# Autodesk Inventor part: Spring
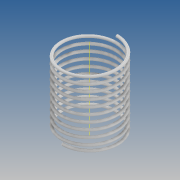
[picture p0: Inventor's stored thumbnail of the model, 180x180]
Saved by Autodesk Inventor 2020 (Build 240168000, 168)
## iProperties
Created: 2019-10
Part Number: Spring
Material: Generic
Document SubType Name: Modeling
Designer: yello
Density: 1 g/cm^3
Appearance: Default
Author: yello
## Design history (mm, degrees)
sketch "Sketch1"
  geometry: L1 (0, 0)-(8, 0); L2 (0, 0)-(0, 3.1); C1 r 0.15 at (0, 3.1)
  constraints: 4 end point, 1 centre point, 1 coincident, 1 horizontal, 1 vertical
  dimensions: "d0" = 8 distance of L1.start L1.end; "d1" = 3.1 distance of L1.start L2.end; "d2" = 0.3 diameter of C1
coil "Coil1" sketch "Sketch1" pitch "d3" = 0.75; turns "d5" = 10; dims "d4" = 10, "d6" = 0, angle "d7" = 90 deg, angle "d8" = 90 deg, "d9" = 0, "d10" = 0
body "Solid1"
